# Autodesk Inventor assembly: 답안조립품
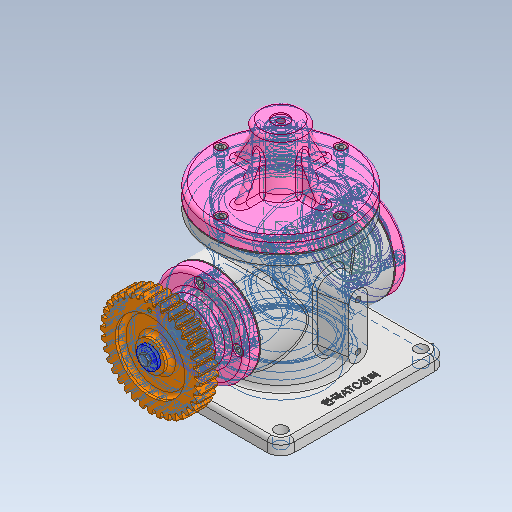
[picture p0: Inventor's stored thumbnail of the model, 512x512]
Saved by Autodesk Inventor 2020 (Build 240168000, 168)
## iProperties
Created: 2020-12
Part Number: 답안조립품
Document SubType Name: Assembly
Designer: USER
Mass: 2325.76 g
Surface Area: 2327.81 cm^2
Volume: 694.974 cm^3
Density: 3.34655 g/cm^3
Author: USER
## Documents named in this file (21)
- C:\Users\USER\Desktop\601206V1034\답안조립품.iam
- C:\Users\USER\Desktop\601206V1034\본체.ipt
- C:\Users\USER\Desktop\601206V1034\E-링.ipt
- C:\Users\USER\Desktop\601206V1034\개스킷 A.ipt
- C:\Users\USER\Desktop\601206V1034\개스킷 B.ipt
- C:\Users\USER\Desktop\601206V1034\덮개.ipt
- C:\Users\USER\Desktop\601206V1034\뒤커버.ipt
- C:\Users\USER\Desktop\601206V1034\링크.ipt
- C:\Users\USER\Desktop\601206V1034\베어링 17 x 40 x 12.ipt
- C:\Users\USER\Desktop\601206V1034\볼트 M4 x 10.ipt
- C:\Users\USER\Desktop\601206V1034\스퍼기어.ipt
- C:\Users\USER\Desktop\601206V1034\슬라이더.ipt
- C:\Users\USER\Desktop\601206V1034\앞커버.ipt
- C:\Users\USER\Desktop\601206V1034\오일 실 17 30 8.ipt
- C:\Users\USER\Desktop\601206V1034\와셔 4x16.ipt
- C:\Users\USER\Desktop\601206V1034\육각 소켓 머리 볼트 M4 x 10.ipt
- C:\Users\USER\Desktop\601206V1034\클레비스 핀 6 x 22.ipt
- 클레비스 핀 6 x 22.ipt
- C:\Users\USER\Desktop\601206V1034\키 4 x 4 x 18.ipt
- C:\Users\USER\Desktop\601206V1034\편심축.ipt
- C:\Users\USER\Desktop\601206V1034\가변스프링.ipt
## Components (5 placed, 4 different names)
1. E-링:1
2. 개스킷 A:1
3. 개스킷 B:1
4. 가변스프링:1
5. 개스킷 A:2
